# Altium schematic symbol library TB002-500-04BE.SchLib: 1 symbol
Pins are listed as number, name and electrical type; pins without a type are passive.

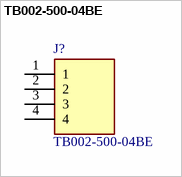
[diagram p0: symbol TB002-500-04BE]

## TB002-500-04BE
designator J?
Fixed Terminal Blocks screw type, 5.00 , horizontal, 4 poles, CUI Blue, slotted screw, PCB mount; Manufacturer_Name: CUI Devices; Geometry.Height: 10mm
footprint TB00250004BE
pins: 1, 2, 3, 4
